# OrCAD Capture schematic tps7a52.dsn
size A
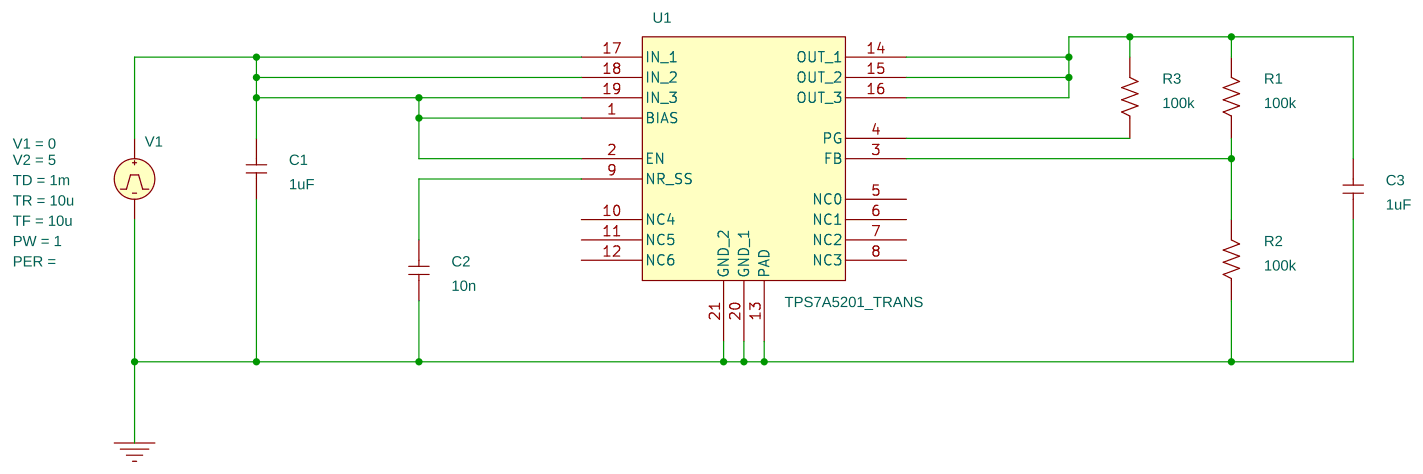
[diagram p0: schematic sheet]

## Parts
C1  1uF  [cap196]
C2  10n  [cap196]
C3  1uF  [cap196]
R1  100k  [AXRC05]
R2  100k  [AXRC05]
R3  100k  [AXRC05]
U1  TPS7A5201_TRANS
V1  VPULSE

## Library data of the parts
C1-C3 = C
R1-R3 = R
U1 = TPS7A5201_TRANS_1
V1 = VPULSE: PW: 1; TD: 1m; TF: 10u; TR: 10u; V1: 0; V2: 5

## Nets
0: C1.1 C2.1 C3.1 R2.1 U1.13(PAD) U1.20(GND_1) U1.21(GND_2) V1.2(-)
N00381: C1.2 U1.1(BIAS) U1.2(EN) U1.17(IN_1) U1.18(IN_2) U1.19(IN_3) V1.1(+)
N00720: C2.2 U1.9(NR_SS)
N00772: C3.2 R1.2 R3.2 U1.14(OUT_1) U1.15(OUT_2) U1.16(OUT_3)
N00920: R1.1 R2.2 U1.3(FB)
N01401: R3.1 U1.4(PG)

Not connected (* = marked no-connect by the designer): U1 5(NC0) 6(NC1) 7(NC2) 8(NC3) 10(NC4) 11(NC5) 12(NC6)
